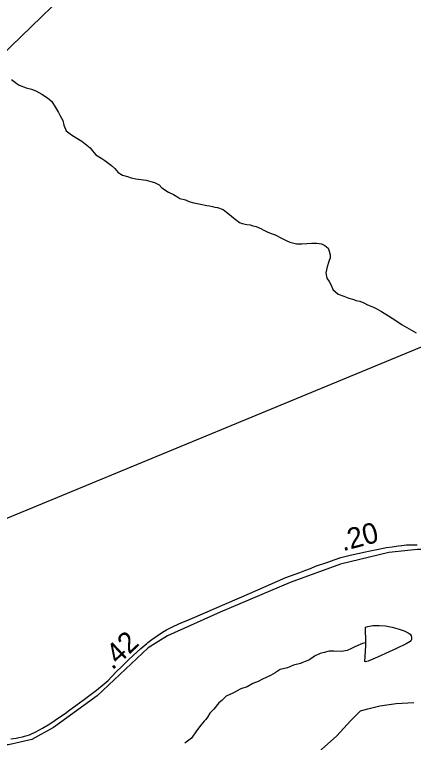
# Model space of a CAD drawing. Extents: x 2001466 to 2224147, y 644118 to 847247.
# Drawn here: x 2035120 to 2037534, y 693236 to 697641 of the extents above; entities that cross this region are included whole.
import ezdxf

# ---------------------------------------------------------------- set-up
doc = ezdxf.new("R2010")
doc.units = 0
for name, color, linetype in [('Exist Boundary Political City Limit New', 7, 'Continuous'), ('Exist Hydrographic Misc Water Feature', 7, 'Continuous'), ('Exist Road Non-System Type 51', 7, 'Continuous'), ('Exist Road Secondary Mileage Hundredths English Label', 7, 'Continuous'), ('Exist Road Secondary Type 51 Attributed', 7, 'Continuous'), ('Exist Utilities Electrical Transmission Line', 7, 'Continuous'), ('Map Preparation Boundary City Limit Buffer Line', 7, 'Continuous')]:
    doc.layers.add(name, color=color, linetype=linetype)

msp = doc.modelspace()

# ---------------------------------------------------------------- linework, layer by layer
at = {"layer": 'Exist Boundary Political City Limit New'}
for points in [[(2035762.2, 693690.1), (2035808, 693734.5), (2035836.8, 693762.6), (2035883.9, 693805.3), (2035920.9, 693835.8), (2035926.4, 693840.8), (2035950.5, 693858.4), (2036015.8, 693902.4), (2036040, 693918.1), (2036076.4, 693936.6), (2036113.2, 693953.6), (2036195.6, 693989.1), (2036540.5, 694137.8), (2036762.2, 694233.4), (2036846.1, 694264.4), (2036875.6, 694276.1), (2036910.4, 694289.4), (2036941.6, 694302.3), (2037016.1, 694327.5), (2037054.8, 694341.6), (2037095, 694354.4), (2037151.4, 694368.7), (2037243.1, 694390.1), (2037262.2, 694393.8), (2037302.8, 694401.6), (2037370.9, 694415.1), (2037404.4, 694420.3), (2037428.1, 694423.9), (2037442.4, 694425.7), (2037462.5, 694428), (2037491.5, 694431), (2037517.2, 694431), (2037557, 694432.5)], [(2035097.5, 693257.2), (2035129.4, 693261.6), (2035144.9, 693265.7), (2035166.9, 693269.5), (2035179.6, 693273.2), (2035196.2, 693277.6), (2035209, 693281.8), (2035221.8, 693287.6), (2035244.6, 693299), (2035266.8, 693310.8), (2035288.1, 693322.6), (2035332.4, 693348.9), (2035397.4, 693392.8), (2035425.5, 693410.8), (2035454.1, 693432.7), (2035490, 693459.4), (2035534, 693491), (2035615.9, 693552.2), (2035662.8, 693591.6), (2035685.5, 693611.7), (2035705.9, 693632.2), (2035737.8, 693666.8), (2035762.2, 693690.1)]]:
    msp.add_lwpolyline(points, dxfattribs=at)
at = {"layer": 'Exist Hydrographic Misc Water Feature'}
for points in [[(2035100.3, 697248.3), (2035124.3, 697230.3), (2035136.2, 697222.3), (2035148.3, 697214.4), (2035190.3, 697198.4), (2035222.3, 697188.4), (2035248.1, 697178.4), (2035284.2, 697158.4), (2035318.3, 697136.5), (2035344.3, 697114.5), (2035368.3, 697078.5), (2035386.3, 697048.5), (2035396.4, 697028.5), (2035412.4, 697000.5), (2035418.3, 696970.5), (2035432.3, 696936.6), (2035464.3, 696912.5), (2035496.3, 696892.6), (2035526.4, 696874.6), (2035556.3, 696850.7), (2035576.4, 696834.6), (2035590.4, 696816.7), (2035612.3, 696792.7), (2035648.4, 696770.7), (2035666.5, 696756.7), (2035706.4, 696726.7), (2035726.5, 696708.8), (2035746.4, 696684.8), (2035772.5, 696668.8), (2035802.4, 696660.8), (2035824.5, 696652.9), (2035854.5, 696646.9), (2035916.4, 696638.9), (2035944.5, 696630.9), (2035966.4, 696624.9), (2035994.5, 696610.9), (2036010.5, 696593), (2036050.5, 696567), (2036080.5, 696551.1), (2036102.4, 696539.1), (2036120.4, 696527.1), (2036154.5, 696519.1), (2036174.4, 696509.1), (2036204.5, 696501.1), (2036244.5, 696493.1), (2036282.4, 696485.2), (2036298.4, 696483.2), (2036316.5, 696479.2), (2036332.5, 696475.2), (2036348.5, 696473.2), (2036382.5, 696461.2), (2036402.4, 696445.3), (2036420.4, 696431.3), (2036444.4, 696411.3), (2036454.5, 696403.3), (2036480.5, 696383.3), (2036496.5, 696377.3), (2036524.4, 696371.3), (2036544.5, 696369.3), (2036562.5, 696361.4), (2036582.4, 696357.4), (2036614.4, 696343.4), (2036618.5, 696339.4), (2036628.3, 696335.4), (2036652.5, 696323.5), (2036678.6, 696313.5), (2036696.4, 696307.5), (2036734.6, 696287.5), (2036762.7, 696273.5), (2036784.6, 696263.5), (2036826.6, 696253.6), (2036858.4, 696253.6), (2036888.4, 696255.6), (2036916.4, 696257.6), (2036948.4, 696257.6), (2036962.4, 696255.6), (2036976.5, 696253.6), (2036996.4, 696243.6)], [(2036996.4, 696243.6), (2037016.5, 696227.6), (2037022.7, 696209.6), (2037028.6, 696187.7), (2037028.6, 696167.7), (2037020.6, 696145.7), (2037010.6, 696113.7), (2037006.5, 696095.7), (2037002.6, 696077.7), (2037008.5, 696045.7), (2037022.7, 696025.7), (2037032.7, 696007.7), (2037042.8, 695983.8), (2037046.7, 695978), (2037078.8, 695947.9), (2037113.1, 695936.5), (2037143.2, 695924.9), (2037173.4, 695916.6), (2037185.3, 695910.9), (2037209.3, 695907.1)], [(2037209.3, 695907.1), (2037233.3, 695897.1), (2037255.4, 695885.2), (2037271.4, 695877.2), (2037291.3, 695869.2), (2037307.3, 695861.3), (2037339.5, 695843.3), (2037383.4, 695817.4), (2037427.4, 695789.4), (2037465.6, 695763.6), (2037493.5, 695747.6), (2037549.6, 695715.7)], [(2037245.1, 693839.5), (2037242.9, 693933.5), (2037256.8, 693937.5), (2037287, 693943.5), (2037327, 693943.6), (2037364.9, 693941.6), (2037404.9, 693933.7), (2037446.9, 693921.8), (2037476.9, 693911.9), (2037501.1, 693899.9), (2037512.9, 693891.9), (2037519.1, 693881.9), (2037520.9, 693872), (2037520.9, 693866), (2037520.9, 693860), (2037519.1, 693854), (2037512.9, 693846), (2037489.2, 693831.9), (2037431.1, 693803.8), (2037387, 693783.7), (2037315.3, 693751.6), (2037259.3, 693727.5), (2037243.3, 693723.4), (2037239.2, 693725.4), (2037245.1, 693821.5), (2037245.1, 693839.5)], [(2037211.1, 693829.4), (2037179.1, 693815.5), (2037151.2, 693799.9), (2037133.4, 693792.2), (2037097.7, 693787), (2037051.8, 693787.9), (2037023.9, 693788.1), (2036994, 693780), (2036970, 693774), (2036934.1, 693758), (2036903.9, 693736), (2036877.9, 693726), (2036858, 693718), (2036850, 693714), (2036808, 693704), (2036772.1, 693687.9), (2036726, 693677.9), (2036696, 693657.8), (2036667.9, 693641.8), (2036619.9, 693619.8), (2036594.1, 693605.8), (2036562.1, 693591.8), (2036528.1, 693571.8), (2036488.1, 693559.8), (2036440.1, 693533.7), (2036400.1, 693515.7), (2036374.1, 693489.7), (2036356, 693475.7), (2036326.3, 693437.7), (2036302.3, 693413.6), (2036288.2, 693389.7), (2036276.3, 693375.7), (2036266.2, 693365.6), (2036246.3, 693339.6), (2036220.3, 693305.6), (2036190.4, 693261.6), (2036150.4, 693231.6)], [(2037245.1, 693839.5), (2037225.1, 693835.4), (2037211.1, 693829.4)]]:
    msp.add_lwpolyline(points, dxfattribs=at)
at = {"layer": 'Exist Road Non-System Type 51'}
msp.add_lwpolyline([(2035564.2, 690800.7), (2036399, 692489.7), (2036444.9, 692553.8), (2036509, 692635.9), (2036550.8, 692703.8), (2036609, 692779.9), (2036634.9, 692823.9), (2036670.8, 692887.8), (2036714.8, 692949.9), (2036762.7, 693004), (2036816.7, 693049.9), (2036870.7, 693102), (2036976.6, 693194), (2037070.7, 693276.1), (2037152.6, 693366.1), (2037212.5, 693428.1), (2037257.7, 693439.1), (2037297.9, 693450.3), (2037330.1, 693457.7), (2037386.3, 693466.5), (2037428.4, 693471.7), (2037536.5, 693477.5)], dxfattribs=at)
at = {"layer": 'Exist Road Secondary Type 51 Attributed'}
msp.add_lwpolyline([(2038786.2, 694537.2), (2038720.8, 694490.7), (2038632.1, 694445.3), (2038545, 694421), (2038386.7, 694404.1), (2037558, 694403), (2037384.9, 694385.1), (2037093, 694314.3), (2036787.9, 694203.4), (2036363.1, 694023.8), (2036044.3, 693882.2), (2035928.1, 693808.3), (2035618.8, 693518.9), (2035355.5, 693325.5), (2035224.6, 693253.7), (2035083.1, 693222), (2034857.2, 693222), (2034469.8, 693242.1), (2034235.4, 693262.2), (2034087.1, 693300.2), (2033812.7, 693410), (2033624.8, 693460.8), (2033470.6, 693477.7), (2032848.5, 693515.5)], dxfattribs=at)
at = {"layer": 'Exist Utilities Electrical Transmission Line'}
for points in [[(2033499.3, 696037.5), (2033602, 696006.1), (2033863.4, 696258.6), (2034348.3, 696725.8), (2034849, 697209), (2035467.7, 697808.5), (2036175.9, 698510.3), (2037148.1, 699464.1)], [(2032364.5, 693503.1), (2034681.8, 694431.6), (2038664.9, 696078), (2040380.3, 696785.9)]]:
    msp.add_lwpolyline(points, dxfattribs=at)
at = {"layer": 'Map Preparation Boundary City Limit Buffer Line'}
for points in [[(2035762.2, 693690.1), (2035808, 693734.5), (2035836.8, 693762.6), (2035883.9, 693805.3), (2035920.9, 693835.8), (2035926.4, 693840.8), (2035950.5, 693858.4), (2036015.8, 693902.4), (2036040, 693918.1), (2036076.4, 693936.6), (2036113.2, 693953.6), (2036195.6, 693989.1), (2036540.5, 694137.8), (2036762.2, 694233.4), (2036846.1, 694264.4), (2036875.6, 694276.1), (2036910.4, 694289.4), (2036941.6, 694302.3), (2037016.1, 694327.5), (2037054.8, 694341.6), (2037095, 694354.4), (2037151.4, 694368.7), (2037243.1, 694390.1), (2037262.2, 694393.8), (2037302.8, 694401.6), (2037370.9, 694415.1), (2037404.4, 694420.3), (2037428.1, 694423.9), (2037442.4, 694425.7), (2037462.5, 694428), (2037491.5, 694431), (2037517.2, 694431), (2037557, 694432.5)], [(2035097.5, 693257.2), (2035129.4, 693261.6), (2035144.9, 693265.7), (2035166.9, 693269.5), (2035179.6, 693273.2), (2035196.2, 693277.6), (2035209, 693281.8), (2035221.8, 693287.6), (2035244.6, 693299), (2035266.8, 693310.8), (2035288.1, 693322.6), (2035332.4, 693348.9), (2035397.4, 693392.8), (2035425.5, 693410.8), (2035454.1, 693432.7), (2035490, 693459.4), (2035534, 693491), (2035615.9, 693552.2), (2035662.8, 693591.6), (2035685.5, 693611.7), (2035705.9, 693632.2), (2035737.8, 693666.8), (2035762.2, 693690.1)]]:
    msp.add_lwpolyline(points, dxfattribs=at)

# ---------------------------------------------------------------- texts
at = {"layer": 'Exist Road Secondary Mileage Hundredths English Label'}
for s, rotation, p in [('.20', 14.8091, (2037106.9, 694392.4)), ('.42', 43.2632, (2035711.4, 693670.4))]:
    msp.add_text(s, height=125, rotation=rotation, dxfattribs=at).set_placement(p)

doc.saveas('drawing.dxf')
